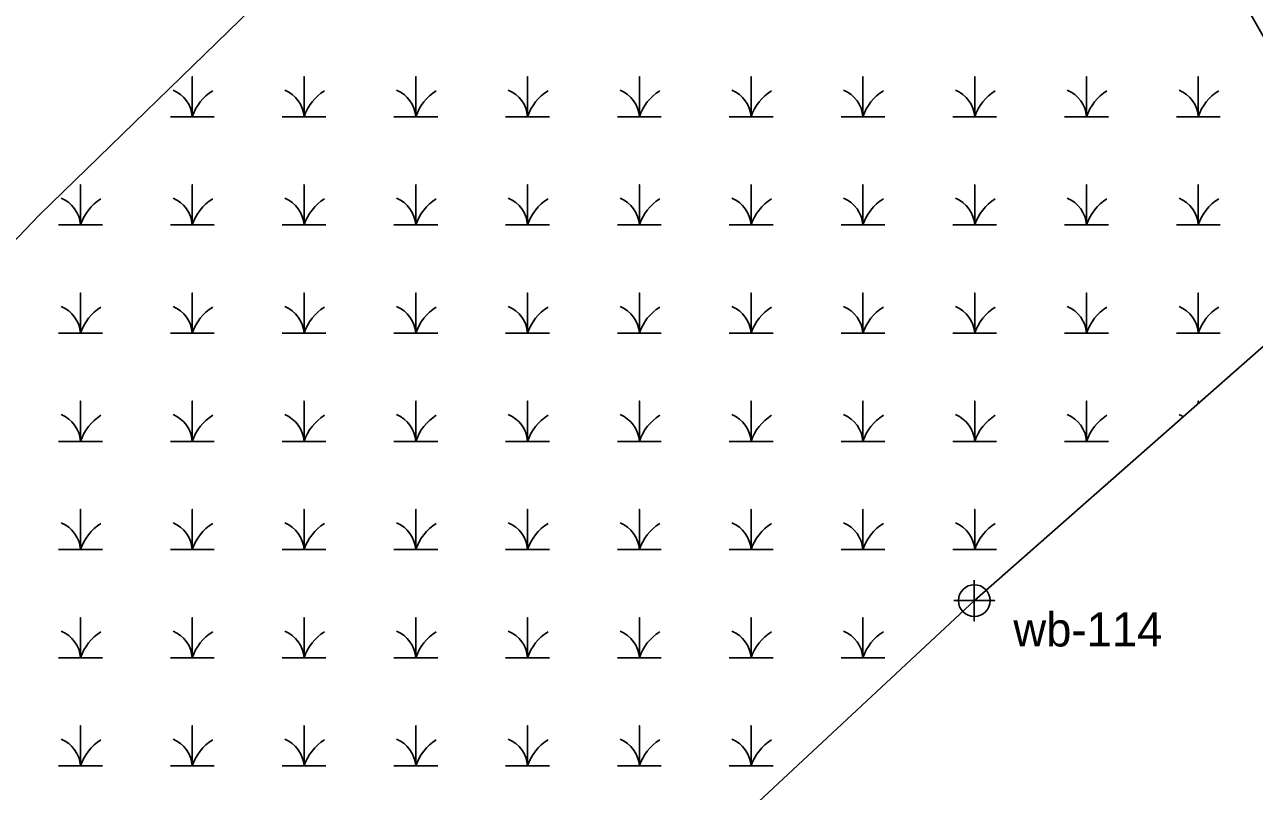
# Model space of a CAD drawing. Extents: x 2379288 to 2381905, y 330670 to 333511.
# Drawn here: x 2380487.2 to 2380668.2, y 332675.5 to 332788.3 of the extents above; entities that cross this region are included whole.
import ezdxf

# ---------------------------------------------------------------- set-up
doc = ezdxf.new("R2010")
doc.units = 0
for name, color, linetype in [('Default', 7, 'Continuous'), ('Exist Environmental Wetland Boundary', 7, 'Continuous'), ('Exist Environmental Wetland Boundary Cogo Number', 7, 'Continuous'), ('Exist Environmental Wetland Boundary Cogo Point CELL', 7, 'Continuous'), ('Exist Hydro Swamp or Marsh', 7, 'Continuous')]:
    doc.layers.add(name, color=color, linetype=linetype)

msp = doc.modelspace()

# ---------------------------------------------------------------- linework, layer by layer
at = {"layer": 'Default'}
msp.add_lwpolyline([(2379288.07, 330873.37), (2380109.3, 332268.58), (2380147.86, 332331.82), (2380190.73, 332397.51), (2380235.65, 332461.81), (2380282.57, 332524.66), (2380331.46, 332586), (2380382.25, 332645.77), (2380434.91, 332703.9), (2380489.37, 332760.35), (2380545.59, 332815.05), (2380603.5, 332867.95), (2380663.06, 332918.99), (2380724.19, 332968.13), (2380786.85, 333015.32), (2380850.96, 333060.51), (2380916.47, 333103.65)], dxfattribs=at)
at = {"layer": 'Exist Environmental Wetland Boundary'}
msp.add_lwpolyline([(2380604.8, 332868.97), (2380606.54, 332870.55), (2380633.85, 332850.01), (2380678.79, 332838.07), (2380664.67, 332795.06), (2380686.7, 332756.16), (2380626.94, 332703.59), (2380578.61, 332658.53)], dxfattribs=at)
at = {"layer": 'Exist Environmental Wetland Boundary Cogo Point CELL'}
msp.add_lwpolyline([(2380626.93, 332706.59), (2380626.93, 332700.59), (2380626.93, 332703.59), (2380629.93, 332703.59), (2380623.93, 332703.59)], dxfattribs=at)
msp.add_circle((2380626.93, 332703.59), 2.34, dxfattribs=at)
at = {"layer": 'Exist Hydro Swamp or Marsh'}
for points in [[(2380508.61, 332774.78), (2380511.84, 332774.78), (2380511.84, 332780.69), (2380511.84, 332774.78), (2380515.06, 332774.78)], [(2380525.06, 332774.78), (2380528.29, 332774.78), (2380528.29, 332780.69), (2380528.29, 332774.78), (2380531.51, 332774.78)], [(2380541.51, 332774.78), (2380544.74, 332774.78), (2380544.74, 332780.69), (2380544.74, 332774.78), (2380547.96, 332774.78)], [(2380557.96, 332774.78), (2380561.19, 332774.78), (2380561.19, 332780.69), (2380561.19, 332774.78), (2380564.42, 332774.78)], [(2380574.42, 332774.78), (2380577.64, 332774.78), (2380577.64, 332780.69), (2380577.64, 332774.78), (2380580.87, 332774.78)], [(2380590.87, 332774.78), (2380594.09, 332774.78), (2380594.09, 332780.69), (2380594.09, 332774.78), (2380597.32, 332774.78)], [(2380607.32, 332774.78), (2380610.54, 332774.78), (2380610.54, 332780.69), (2380610.54, 332774.78), (2380613.77, 332774.78)], [(2380623.77, 332774.78), (2380626.99, 332774.78), (2380626.99, 332780.69), (2380626.99, 332774.78), (2380630.22, 332774.78)], [(2380640.22, 332774.78), (2380643.45, 332774.78), (2380643.45, 332780.69), (2380643.45, 332774.78), (2380646.67, 332774.78)], [(2380656.67, 332774.78), (2380659.9, 332774.78), (2380659.9, 332780.69), (2380659.9, 332774.78), (2380663.12, 332774.78)], [(2380492.16, 332758.86), (2380495.38, 332758.86), (2380495.38, 332764.78), (2380495.38, 332758.86), (2380498.61, 332758.86)], [(2380508.61, 332758.86), (2380511.84, 332758.86), (2380511.84, 332764.78), (2380511.84, 332758.86), (2380515.06, 332758.86)], [(2380525.06, 332758.86), (2380528.29, 332758.86), (2380528.29, 332764.78), (2380528.29, 332758.86), (2380531.51, 332758.86)], [(2380541.51, 332758.86), (2380544.74, 332758.86), (2380544.74, 332764.78), (2380544.74, 332758.86), (2380547.96, 332758.86)], [(2380557.96, 332758.86), (2380561.19, 332758.86), (2380561.19, 332764.78), (2380561.19, 332758.86), (2380564.42, 332758.86)], [(2380574.42, 332758.86), (2380577.64, 332758.86), (2380577.64, 332764.78), (2380577.64, 332758.86), (2380580.87, 332758.86)], [(2380590.87, 332758.86), (2380594.09, 332758.86), (2380594.09, 332764.78), (2380594.09, 332758.86), (2380597.32, 332758.86)], [(2380607.32, 332758.86), (2380610.54, 332758.86), (2380610.54, 332764.78), (2380610.54, 332758.86), (2380613.77, 332758.86)], [(2380623.77, 332758.86), (2380626.99, 332758.86), (2380626.99, 332764.78), (2380626.99, 332758.86), (2380630.22, 332758.86)], [(2380640.22, 332758.86), (2380643.45, 332758.86), (2380643.45, 332764.78), (2380643.45, 332758.86), (2380646.67, 332758.86)], [(2380656.67, 332758.86), (2380659.9, 332758.86), (2380659.9, 332764.78), (2380659.9, 332758.86), (2380663.12, 332758.86)], [(2380492.16, 332742.94), (2380495.38, 332742.94), (2380495.38, 332748.86), (2380495.38, 332742.94), (2380498.61, 332742.94)], [(2380508.61, 332742.94), (2380511.84, 332742.94), (2380511.84, 332748.86), (2380511.84, 332742.94), (2380515.06, 332742.94)], [(2380525.06, 332742.94), (2380528.29, 332742.94), (2380528.29, 332748.86), (2380528.29, 332742.94), (2380531.51, 332742.94)], [(2380541.51, 332742.94), (2380544.74, 332742.94), (2380544.74, 332748.86), (2380544.74, 332742.94), (2380547.96, 332742.94)], [(2380557.96, 332742.94), (2380561.19, 332742.94), (2380561.19, 332748.86), (2380561.19, 332742.94), (2380564.42, 332742.94)], [(2380574.42, 332742.94), (2380577.64, 332742.94), (2380577.64, 332748.86), (2380577.64, 332742.94), (2380580.87, 332742.94)], [(2380590.87, 332742.94), (2380594.09, 332742.94), (2380594.09, 332748.86), (2380594.09, 332742.94), (2380597.32, 332742.94)], [(2380607.32, 332742.94), (2380610.54, 332742.94), (2380610.54, 332748.86), (2380610.54, 332742.94), (2380613.77, 332742.94)], [(2380623.77, 332742.94), (2380626.99, 332742.94), (2380626.99, 332748.86), (2380626.99, 332742.94), (2380630.22, 332742.94)], [(2380640.22, 332742.94), (2380643.45, 332742.94), (2380643.45, 332748.86), (2380643.45, 332742.94), (2380646.67, 332742.94)], [(2380656.67, 332742.94), (2380659.9, 332742.94), (2380659.9, 332748.86), (2380659.9, 332742.94), (2380663.12, 332742.94)], [(2380492.16, 332727.02), (2380495.38, 332727.02), (2380495.38, 332732.94), (2380495.38, 332727.02), (2380498.61, 332727.02)], [(2380508.61, 332727.02), (2380511.84, 332727.02), (2380511.84, 332732.94), (2380511.84, 332727.02), (2380515.06, 332727.02)], [(2380525.06, 332727.02), (2380528.29, 332727.02), (2380528.29, 332732.94), (2380528.29, 332727.02), (2380531.51, 332727.02)], [(2380541.51, 332727.02), (2380544.74, 332727.02), (2380544.74, 332732.94), (2380544.74, 332727.02), (2380547.96, 332727.02)], [(2380557.96, 332727.02), (2380561.19, 332727.02), (2380561.19, 332732.94), (2380561.19, 332727.02), (2380564.42, 332727.02)], [(2380574.42, 332727.02), (2380577.64, 332727.02), (2380577.64, 332732.94), (2380577.64, 332727.02), (2380580.87, 332727.02)], [(2380590.87, 332727.02), (2380594.09, 332727.02), (2380594.09, 332732.94), (2380594.09, 332727.02), (2380597.32, 332727.02)], [(2380607.32, 332727.02), (2380610.54, 332727.02), (2380610.54, 332732.94), (2380610.54, 332727.02), (2380613.77, 332727.02)], [(2380623.77, 332727.02), (2380626.99, 332727.02), (2380626.99, 332732.94), (2380626.99, 332727.02), (2380630.22, 332727.02)], [(2380640.22, 332727.02), (2380643.45, 332727.02), (2380643.45, 332732.94), (2380643.45, 332727.02), (2380646.67, 332727.02)], [(2380659.9, 332732.58), (2380659.9, 332732.94), (2380659.9, 332732.58)], [(2380492.16, 332711.1), (2380495.38, 332711.1), (2380495.38, 332717.02), (2380495.38, 332711.1), (2380498.61, 332711.1)], [(2380508.61, 332711.1), (2380511.84, 332711.1), (2380511.84, 332717.02), (2380511.84, 332711.1), (2380515.06, 332711.1)], [(2380525.06, 332711.1), (2380528.29, 332711.1), (2380528.29, 332717.02), (2380528.29, 332711.1), (2380531.51, 332711.1)], [(2380541.51, 332711.1), (2380544.74, 332711.1), (2380544.74, 332717.02), (2380544.74, 332711.1), (2380547.96, 332711.1)], [(2380557.96, 332711.1), (2380561.19, 332711.1), (2380561.19, 332717.02), (2380561.19, 332711.1), (2380564.42, 332711.1)], [(2380574.42, 332711.1), (2380577.64, 332711.1), (2380577.64, 332717.02), (2380577.64, 332711.1), (2380580.87, 332711.1)], [(2380590.87, 332711.1), (2380594.09, 332711.1), (2380594.09, 332717.02), (2380594.09, 332711.1), (2380597.32, 332711.1)], [(2380607.32, 332711.1), (2380610.54, 332711.1), (2380610.54, 332717.02), (2380610.54, 332711.1), (2380613.77, 332711.1)], [(2380623.77, 332711.1), (2380626.99, 332711.1), (2380626.99, 332717.02), (2380626.99, 332711.1), (2380630.22, 332711.1)], [(2380492.16, 332695.19), (2380495.38, 332695.19), (2380495.38, 332701.1), (2380495.38, 332695.19), (2380498.61, 332695.19)], [(2380508.61, 332695.19), (2380511.84, 332695.19), (2380511.84, 332701.1), (2380511.84, 332695.19), (2380515.06, 332695.19)], [(2380525.06, 332695.19), (2380528.29, 332695.19), (2380528.29, 332701.1), (2380528.29, 332695.19), (2380531.51, 332695.19)], [(2380541.51, 332695.19), (2380544.74, 332695.19), (2380544.74, 332701.1), (2380544.74, 332695.19), (2380547.96, 332695.19)], [(2380557.96, 332695.19), (2380561.19, 332695.19), (2380561.19, 332701.1), (2380561.19, 332695.19), (2380564.42, 332695.19)], [(2380574.42, 332695.19), (2380577.64, 332695.19), (2380577.64, 332701.1), (2380577.64, 332695.19), (2380580.87, 332695.19)], [(2380590.87, 332695.19), (2380594.09, 332695.19), (2380594.09, 332701.1), (2380594.09, 332695.19), (2380597.32, 332695.19)], [(2380607.32, 332695.19), (2380610.54, 332695.19), (2380610.54, 332701.1), (2380610.54, 332695.19), (2380613.77, 332695.19)], [(2380492.16, 332679.27), (2380495.38, 332679.27), (2380495.38, 332685.19), (2380495.38, 332679.27), (2380498.61, 332679.27)], [(2380508.61, 332679.27), (2380511.84, 332679.27), (2380511.84, 332685.19), (2380511.84, 332679.27), (2380515.06, 332679.27)], [(2380525.06, 332679.27), (2380528.29, 332679.27), (2380528.29, 332685.19), (2380528.29, 332679.27), (2380531.51, 332679.27)], [(2380541.51, 332679.27), (2380544.74, 332679.27), (2380544.74, 332685.19), (2380544.74, 332679.27), (2380547.96, 332679.27)], [(2380557.96, 332679.27), (2380561.19, 332679.27), (2380561.19, 332685.19), (2380561.19, 332679.27), (2380564.42, 332679.27)], [(2380574.42, 332679.27), (2380577.64, 332679.27), (2380577.64, 332685.19), (2380577.64, 332679.27), (2380580.87, 332679.27)], [(2380590.87, 332679.27), (2380594.09, 332679.27), (2380594.09, 332685.19), (2380594.09, 332679.27), (2380597.32, 332679.27)]]:
    msp.add_lwpolyline(points, dxfattribs=at)
for centre, radius, start, end in [((2380507.24, 332774.44), 4.61, 4.1403, 67.535), ((2380518.68, 332772.5), 7.21, 122.1274, 161.6222), ((2380523.69, 332774.44), 4.61, 4.1403, 67.535), ((2380535.13, 332772.5), 7.21, 122.1274, 161.6222), ((2380540.14, 332774.44), 4.61, 4.1403, 67.535), ((2380551.58, 332772.5), 7.21, 122.1274, 161.6222), ((2380556.59, 332774.44), 4.61, 4.1403, 67.535), ((2380568.03, 332772.5), 7.21, 122.1274, 161.6222), ((2380573.04, 332774.44), 4.61, 4.1403, 67.535), ((2380584.48, 332772.5), 7.21, 122.1274, 161.6222), ((2380589.49, 332774.44), 4.61, 4.1403, 67.535), ((2380600.93, 332772.5), 7.21, 122.1274, 161.6222), ((2380605.94, 332774.44), 4.61, 4.1403, 67.535), ((2380617.38, 332772.5), 7.21, 122.1274, 161.6222), ((2380622.39, 332774.44), 4.61, 4.1403, 67.535), ((2380633.84, 332772.5), 7.21, 122.1274, 161.6222), ((2380638.85, 332774.44), 4.61, 4.1403, 67.535), ((2380650.29, 332772.5), 7.21, 122.1274, 161.6222), ((2380655.3, 332774.44), 4.61, 4.1403, 67.535), ((2380666.74, 332772.5), 7.21, 122.1274, 161.6222), ((2380490.79, 332758.53), 4.61, 4.1403, 67.535), ((2380502.23, 332756.59), 7.21, 122.1274, 161.6222), ((2380507.24, 332758.53), 4.61, 4.1403, 67.535), ((2380518.68, 332756.59), 7.21, 122.1274, 161.6222), ((2380523.69, 332758.53), 4.61, 4.1403, 67.535), ((2380535.13, 332756.59), 7.21, 122.1274, 161.6222), ((2380540.14, 332758.53), 4.61, 4.1403, 67.535), ((2380551.58, 332756.59), 7.21, 122.1274, 161.6222), ((2380556.59, 332758.53), 4.61, 4.1403, 67.535), ((2380568.03, 332756.59), 7.21, 122.1274, 161.6222), ((2380573.04, 332758.53), 4.61, 4.1403, 67.535), ((2380584.48, 332756.59), 7.21, 122.1274, 161.6222), ((2380589.49, 332758.53), 4.61, 4.1403, 67.535), ((2380600.93, 332756.59), 7.21, 122.1274, 161.6222), ((2380605.94, 332758.53), 4.61, 4.1403, 67.535), ((2380617.38, 332756.59), 7.21, 122.1274, 161.6222), ((2380622.39, 332758.53), 4.61, 4.1403, 67.535), ((2380633.84, 332756.59), 7.21, 122.1274, 161.6222), ((2380638.85, 332758.53), 4.61, 4.1403, 67.535), ((2380650.29, 332756.59), 7.21, 122.1274, 161.6222), ((2380655.3, 332758.53), 4.61, 4.1403, 67.535), ((2380666.74, 332756.59), 7.21, 122.1274, 161.6222), ((2380490.79, 332742.61), 4.61, 4.1403, 67.535), ((2380502.23, 332740.67), 7.21, 122.1274, 161.6222), ((2380507.24, 332742.61), 4.61, 4.1403, 67.535), ((2380518.68, 332740.67), 7.21, 122.1274, 161.6222), ((2380523.69, 332742.61), 4.61, 4.1403, 67.535), ((2380535.13, 332740.67), 7.21, 122.1274, 161.6222), ((2380540.14, 332742.61), 4.61, 4.1403, 67.535), ((2380551.58, 332740.67), 7.21, 122.1274, 161.6222), ((2380556.59, 332742.61), 4.61, 4.1403, 67.535), ((2380568.03, 332740.67), 7.21, 122.1274, 161.6222), ((2380573.04, 332742.61), 4.61, 4.1403, 67.535), ((2380584.48, 332740.67), 7.21, 122.1274, 161.6222), ((2380589.49, 332742.61), 4.61, 4.1403, 67.535), ((2380600.93, 332740.67), 7.21, 122.1274, 161.6222), ((2380605.94, 332742.61), 4.61, 4.1403, 67.535), ((2380617.38, 332740.67), 7.21, 122.1274, 161.6222), ((2380622.39, 332742.61), 4.61, 4.1403, 67.535), ((2380633.84, 332740.67), 7.21, 122.1274, 161.6222), ((2380638.85, 332742.61), 4.61, 4.1403, 67.535), ((2380650.29, 332740.67), 7.21, 122.1274, 161.6222), ((2380655.3, 332742.61), 4.61, 4.1403, 67.535), ((2380666.74, 332740.67), 7.21, 122.1274, 161.6222), ((2380490.79, 332726.69), 4.61, 4.1403, 67.535), ((2380502.23, 332724.75), 7.21, 122.1274, 161.6222), ((2380507.24, 332726.69), 4.61, 4.1403, 67.535), ((2380518.68, 332724.75), 7.21, 122.1274, 161.6222), ((2380523.69, 332726.69), 4.61, 4.1403, 67.535), ((2380535.13, 332724.75), 7.21, 122.1274, 161.6222), ((2380540.14, 332726.69), 4.61, 4.1403, 67.535), ((2380551.58, 332724.75), 7.21, 122.1274, 161.6222), ((2380556.59, 332726.69), 4.61, 4.1403, 67.535), ((2380568.03, 332724.75), 7.21, 122.1274, 161.6222), ((2380573.04, 332726.69), 4.61, 4.1403, 67.535), ((2380584.48, 332724.75), 7.21, 122.1274, 161.6222), ((2380589.49, 332726.69), 4.61, 4.1403, 67.535), ((2380600.93, 332724.75), 7.21, 122.1274, 161.6222), ((2380605.94, 332726.69), 4.61, 4.1403, 67.535), ((2380617.38, 332724.75), 7.21, 122.1274, 161.6222), ((2380622.39, 332726.69), 4.61, 4.1403, 67.535), ((2380633.84, 332724.75), 7.21, 122.1274, 161.6222), ((2380638.85, 332726.69), 4.61, 4.1403, 67.535), ((2380650.29, 332724.75), 7.21, 122.1274, 161.6222), ((2380655.3, 332726.69), 4.61, 58.808, 67.535), ((2380490.79, 332710.77), 4.61, 4.1403, 67.535), ((2380502.23, 332708.83), 7.21, 122.1274, 161.6222), ((2380507.24, 332710.77), 4.61, 4.1403, 67.535), ((2380518.68, 332708.83), 7.21, 122.1274, 161.6222), ((2380523.69, 332710.77), 4.61, 4.1403, 67.535), ((2380535.13, 332708.83), 7.21, 122.1274, 161.6222), ((2380540.14, 332710.77), 4.61, 4.1403, 67.535), ((2380551.58, 332708.83), 7.21, 122.1274, 161.6222), ((2380556.59, 332710.77), 4.61, 4.1403, 67.535), ((2380568.03, 332708.83), 7.21, 122.1274, 161.6222), ((2380573.04, 332710.77), 4.61, 4.1403, 67.535), ((2380584.48, 332708.83), 7.21, 122.1274, 161.6222), ((2380589.49, 332710.77), 4.61, 4.1403, 67.535), ((2380600.93, 332708.83), 7.21, 122.1274, 161.6222), ((2380605.94, 332710.77), 4.61, 4.1403, 67.535), ((2380617.38, 332708.83), 7.21, 122.1274, 161.6222), ((2380622.39, 332710.77), 4.61, 4.1403, 67.535), ((2380633.84, 332708.83), 7.21, 122.1274, 161.6222), ((2380490.79, 332694.85), 4.61, 4.1403, 67.535), ((2380502.23, 332692.91), 7.21, 122.1274, 161.6222), ((2380507.24, 332694.85), 4.61, 4.1403, 67.535), ((2380518.68, 332692.91), 7.21, 122.1274, 161.6222), ((2380523.69, 332694.85), 4.61, 4.1403, 67.535), ((2380535.13, 332692.91), 7.21, 122.1274, 161.6222), ((2380540.14, 332694.85), 4.61, 4.1403, 67.535), ((2380551.58, 332692.91), 7.21, 122.1274, 161.6222), ((2380556.59, 332694.85), 4.61, 4.1403, 67.535), ((2380568.03, 332692.91), 7.21, 122.1274, 161.6222), ((2380573.04, 332694.85), 4.61, 4.1403, 67.535), ((2380584.48, 332692.91), 7.21, 122.1274, 161.6222), ((2380589.49, 332694.85), 4.61, 4.1403, 67.535), ((2380600.93, 332692.91), 7.21, 122.1274, 161.6222), ((2380605.94, 332694.85), 4.61, 4.1403, 67.535), ((2380617.38, 332692.91), 7.21, 122.1274, 161.6222), ((2380490.79, 332678.94), 4.61, 4.1403, 67.535), ((2380502.23, 332677), 7.21, 122.1274, 161.6222), ((2380507.24, 332678.94), 4.61, 4.1403, 67.535), ((2380518.68, 332677), 7.21, 122.1274, 161.6222), ((2380523.69, 332678.94), 4.61, 4.1403, 67.535), ((2380535.13, 332677), 7.21, 122.1274, 161.6222), ((2380540.14, 332678.94), 4.61, 4.1403, 67.535), ((2380551.58, 332677), 7.21, 122.1274, 161.6222), ((2380556.59, 332678.94), 4.61, 4.1403, 67.535), ((2380568.03, 332677), 7.21, 122.1274, 161.6222), ((2380573.04, 332678.94), 4.61, 4.1403, 67.535), ((2380584.48, 332677), 7.21, 122.1274, 161.6222), ((2380589.49, 332678.94), 4.61, 4.1403, 67.535), ((2380600.93, 332677), 7.21, 122.1274, 161.6222)]:
    msp.add_arc(centre, radius, start, end, dxfattribs=at)

# ---------------------------------------------------------------- texts
at = {"layer": 'Exist Environmental Wetland Boundary Cogo Number'}
msp.add_text('wb-114', height=5, dxfattribs=at).set_placement((2380632.68, 332696.85))

doc.saveas('drawing.dxf')
